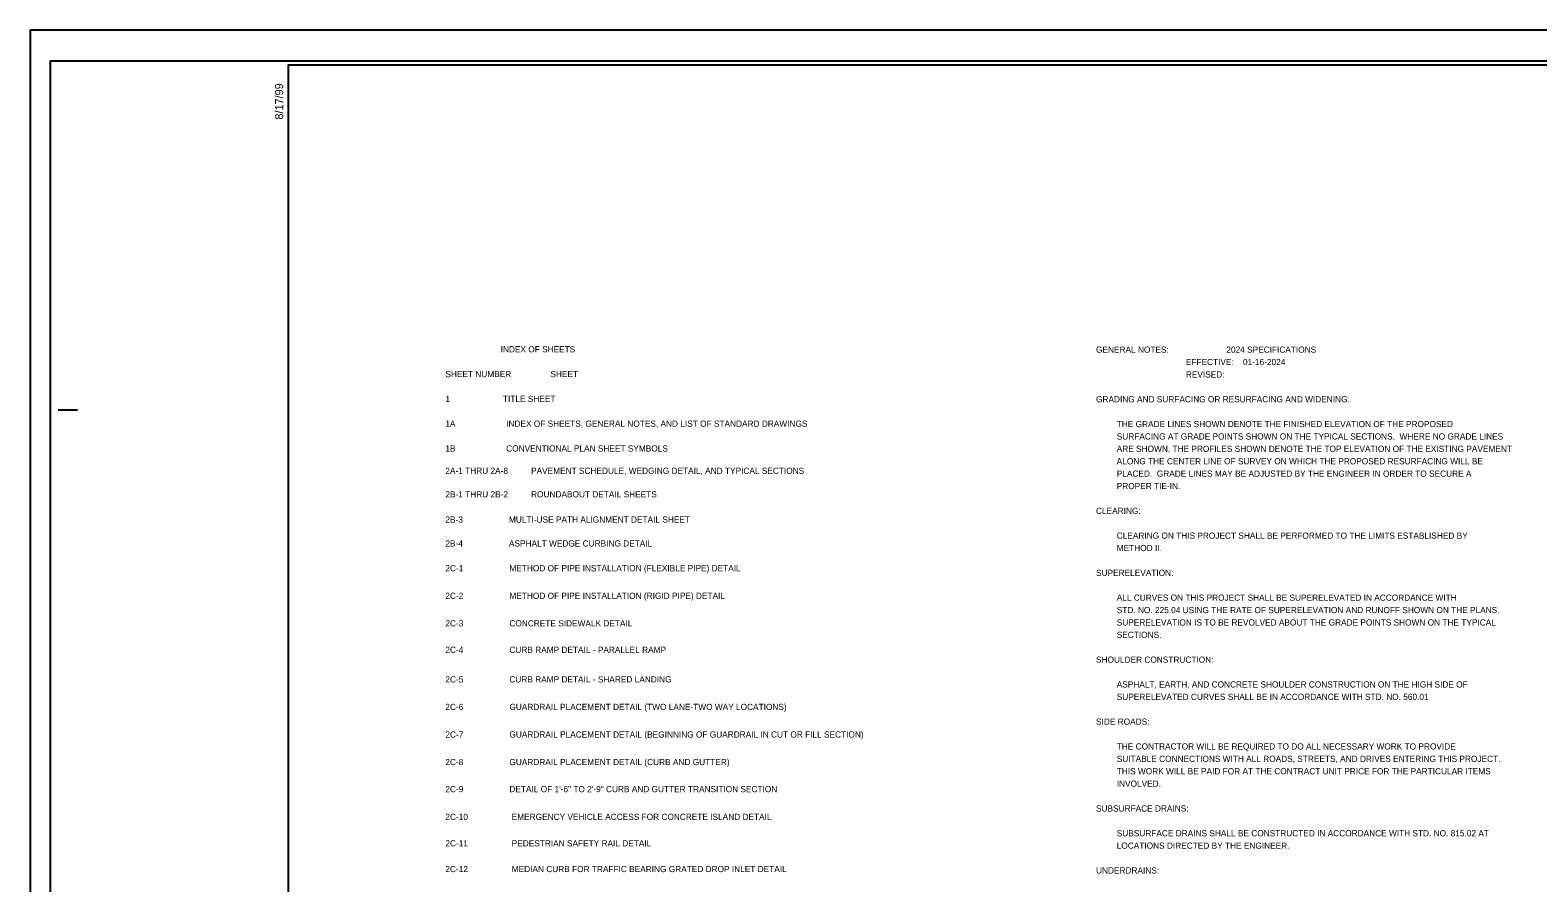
# Model space of a CAD drawing. Extents: x 1537922 to 1539606, y 409903 to 410998.
# Drawn here: x 1537922 to 1538895, y 410448 to 410998 of the extents above; entities that cross this region are included whole.
import ezdxf

# ---------------------------------------------------------------- set-up
doc = ezdxf.new("R2010")
doc.units = 0
for name, color, linetype in [('Old_Level_1', 7, 'Continuous'), ('Sheet Cutting Line CELL', 7, 'Continuous'), ('Sheet Plan CELL', 7, 'Continuous'), ('Sheet Plot Border Inside CELL', 7, 'Continuous'), ('Sheet Plot Border Outside CELL', 7, 'Continuous')]:
    doc.layers.add(name, color=color, linetype=linetype)

msp = doc.modelspace()

# ---------------------------------------------------------------- linework, layer by layer
at = {"layer": 'Sheet Cutting Line CELL'}
for p, q in [((1539605.87, 410998.35), (1537922.37, 410998.35)), ((1537922.37, 410998.35), (1537922.37, 409903.35))]:
    msp.add_line(p, q, dxfattribs=at)
at = {"layer": 'Sheet Plan CELL'}
for p, q in [((1538088.87, 410975.85), (1538088.87, 410975.85)), ((1537940.37, 410753.35), (1537952.87, 410753.35))]:
    msp.add_line(p, q, dxfattribs=at)
msp.add_lwpolyline([(1539588.87, 410975.85), (1538088.87, 410975.85), (1538088.87, 409925.85), (1539588.87, 409925.85)], close=True, dxfattribs=at)
at = {"layer": 'Sheet Plot Border Inside CELL'}
msp.add_lwpolyline([(1537935.37, 409923.35), (1539601.37, 409923.35), (1539601.37, 410978.35), (1537935.37, 410978.35)], close=True, dxfattribs=at)
at = {"layer": 'Sheet Plot Border Outside CELL'}
msp.add_lwpolyline([(1537922.37, 409903.35), (1539605.87, 409903.35), (1539605.87, 410998.35), (1537922.37, 410998.35)], close=True, dxfattribs=at)

# ---------------------------------------------------------------- texts
at = {"layer": 'Old_Level_1'}
for s, p in [('                        INDEX OF SHEETS ', (1538190.28, 410790.48)), ('GENERAL NOTES:                         2024 SPECIFICATIONS', (1538610.1, 410790.24)), ('                                       EFFECTIVE:    01-16-2024', (1538610.1, 410782.24)), ('SHEET NUMBER                 SHEET   ', (1538190.28, 410774.48)), ('                                       REVISED:      ', (1538610.1, 410774.24)), ('1                       TITLE SHEET', (1538190.28, 410758.48)), ('GRADING AND SURFACING OR RESURFACING AND WIDENING:  ', (1538610.1, 410758.24)), ('1A                      INDEX OF SHEETS, GENERAL NOTES, AND LIST OF STANDARD DRAWINGS', (1538190.28, 410742.48)), ('         THE GRADE LINES SHOWN DENOTE THE FINISHED ELEVATION OF THE PROPOSED ', (1538610.1, 410742.24)), ('         SURFACING AT GRADE POINTS SHOWN ON THE TYPICAL SECTIONS.  WHERE NO GRADE LINES ', (1538610.1, 410734.24)), ('1B                      CONVENTIONAL PLAN SHEET SYMBOLS ', (1538190.28, 410726.48)), ('         ARE SHOWN, THE PROFILES SHOWN DENOTE THE TOP ELEVATION OF THE EXISTING PAVEMENT ', (1538610.1, 410726.24)), ('2A-1 THRU 2A-8          PAVEMENT SCHEDULE, WEDGING DETAIL, AND TYPICAL SECTIONS', (1538190.28, 410712.08)), ('         ALONG THE CENTER LINE OF SURVEY ON WHICH THE PROPOSED RESURFACING WILL BE ', (1538610.1, 410718.24)), ('         PLACED.  GRADE LINES MAY BE ADJUSTED BY THE ENGINEER IN ORDER TO SECURE A ', (1538610.1, 410710.24)), ('         PROPER TIE-IN.  ', (1538610.1, 410702.24)), ('2B-1 THRU 2B-2          ROUNDABOUT DETAIL SHEETS', (1538190.28, 410696.92)), ('CLEARING:  ', (1538610.1, 410686.24)), ('2B-3                    MULTI-USE PATH ALIGNMENT DETAIL SHEET', (1538190.28, 410680.62)), ('2B-4                    ASPHALT WEDGE CURBING DETAIL ', (1538190.28, 410665.22)), ('         CLEARING ON THIS PROJECT SHALL BE PERFORMED TO THE LIMITS ESTABLISHED BY ', (1538610.1, 410670.24)), ('         METHOD II.', (1538610.1, 410662.24)), ('2C-1                    METHOD OF PIPE INSTALLATION (FLEXIBLE PIPE) DETAIL', (1538190.28, 410649.23)), ('SUPERELEVATION:  ', (1538610.1, 410646.24)), ('2C-2                    METHOD OF PIPE INSTALLATION (RIGID PIPE) DETAIL', (1538190.28, 410631.45)), ('         ALL CURVES ON THIS PROJECT SHALL BE SUPERELEVATED IN ACCORDANCE WITH', (1538610.1, 410630.24)), ('2C-3                    CONCRETE SIDEWALK DETAIL', (1538190.28, 410613.67)), ('         STD. NO. 225.04 USING THE RATE OF SUPERELEVATION AND RUNOFF SHOWN ON THE PLANS.', (1538610.1, 410622.24)), ('         SUPERELEVATION IS TO BE REVOLVED ABOUT THE GRADE POINTS SHOWN ON THE TYPICAL ', (1538610.1, 410614.24)), ('         SECTIONS.  ', (1538610.1, 410606.24)), ('2C-4                    CURB RAMP DETAIL - PARALLEL RAMP', (1538190.28, 410596.57)), ('SHOULDER CONSTRUCTION:  ', (1538610.1, 410590.24)), ('2C-5                    CURB RAMP DETAIL - SHARED LANDING', (1538190.28, 410577.52)), ('         ASPHALT, EARTH, AND CONCRETE SHOULDER CONSTRUCTION ON THE HIGH SIDE OF', (1538610.1, 410574.24)), ('         SUPERELEVATED CURVES SHALL BE IN ACCORDANCE WITH STD. NO. 560.01', (1538610.1, 410566.24)), ('2C-6                    GUARDRAIL PLACEMENT DETAIL (TWO LANE-TWO WAY LOCATIONS)', (1538190.28, 410559.74)), ('SIDE ROADS:  ', (1538610.1, 410550.24)), ('2C-7                    GUARDRAIL PLACEMENT DETAIL (BEGINNING OF GUARDRAIL IN CUT OR FILL SECTION)', (1538190.28, 410541.96)), ('         THE CONTRACTOR WILL BE REQUIRED TO DO ALL NECESSARY WORK TO PROVIDE ', (1538610.1, 410534.24)), ('         SUITABLE CONNECTIONS WITH ALL ROADS, STREETS, AND DRIVES ENTERING THIS PROJECT.  ', (1538610.1, 410526.24)), ('2C-8                    GUARDRAIL PLACEMENT DETAIL (CURB AND GUTTER)', (1538190.28, 410524.18)), ('         THIS WORK WILL BE PAID FOR AT THE CONTRACT UNIT PRICE FOR THE PARTICULAR ITEMS ', (1538610.1, 410518.24)), ('2C-9                    DETAIL OF 1\'-6" TO 2\'-9" CURB AND GUTTER TRANSITION SECTION', (1538190.28, 410506.72)), ('         INVOLVED.  ', (1538610.1, 410510.24)), ('2C-10                   EMERGENCY VEHICLE ACCESS FOR CONCRETE ISLAND DETAIL', (1538190.28, 410488.81)), ('SUBSURFACE DRAINS:', (1538610.1, 410494.24)), ('         SUBSURFACE DRAINS SHALL BE CONSTRUCTED IN ACCORDANCE WITH STD. NO. 815.02 AT ', (1538610.1, 410478.24)), ('2C-11                   PEDESTRIAN SAFETY RAIL DETAIL', (1538190.28, 410471.76)), ('         LOCATIONS DIRECTED BY THE ENGINEER.  ', (1538610.1, 410470.24)), ('2C-12                   MEDIAN CURB FOR TRAFFIC BEARING GRATED DROP INLET DETAIL', (1538190.28, 410455.15)), ('UNDERDRAINS:  ', (1538610.1, 410454.24))]:
    msp.add_text(s, height=4, dxfattribs=at).set_placement(p)
at = {"layer": 'Sheet Plan CELL'}
msp.add_text('8/17/99', height=5.25, rotation=90, dxfattribs=at).set_placement((1538085.62, 410940.65))

doc.saveas('drawing.dxf')
